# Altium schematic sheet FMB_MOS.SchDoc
size A3
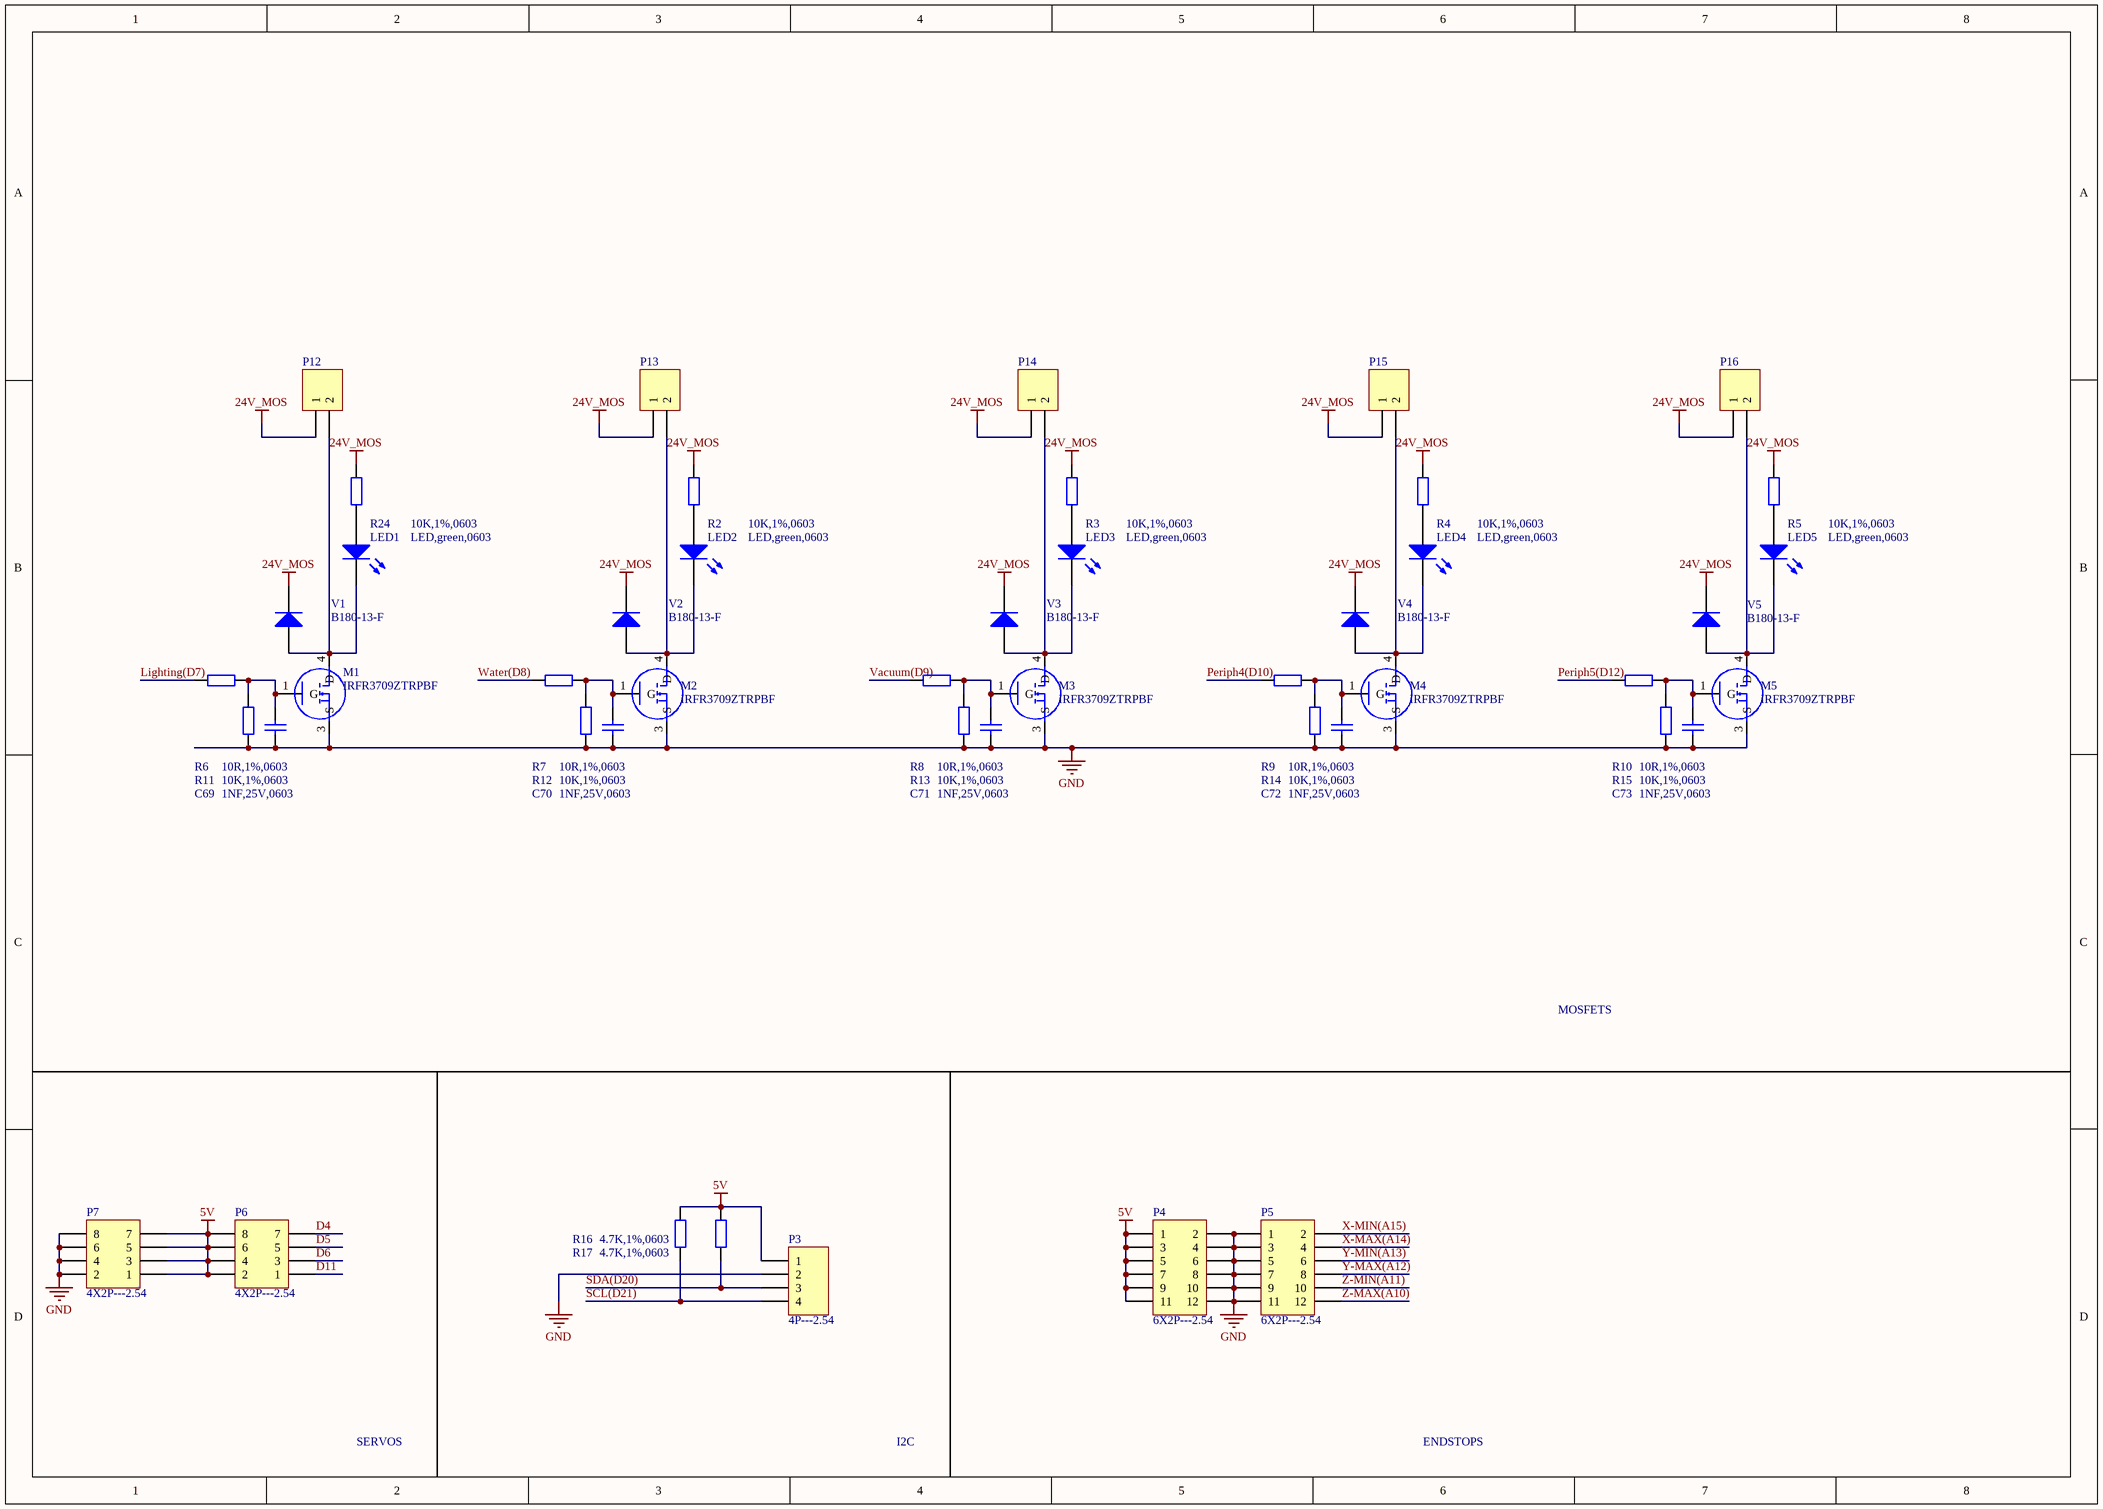
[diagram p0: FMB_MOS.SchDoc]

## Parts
C69  1NF,25V,0603  [RC0603]
C70  1NF,25V,0603  [RC0603]
C71  1NF,25V,0603  [RC0603]
C72  1NF,25V,0603  [RC0603]
C73  1NF,25V,0603  [RC0603]
LED1  LED,green,0603  [LED-0603]
LED2  LED,green,0603  [LED-0603]
LED3  LED,green,0603  [LED-0603]
LED4  LED,green,0603  [LED-0603]
LED5  LED,green,0603  [LED-0603]
M1  IRFR3709ZTRPBF  [DPAK]
M2  IRFR3709ZTRPBF  [DPAK]
M3  IRFR3709ZTRPBF  [DPAK]
M4  IRFR3709ZTRPBF  [DPAK]
M5  IRFR3709ZTRPBF  [DPAK]
P3  4P---2.54  [HDR1X4]
P4  6X2P---2.54  [HDR2X6]
P5  6X2P---2.54  [HDR2X6]
P6  4X2P---2.54  [HDR2X4]
P7  4X2P---2.54  [HDR2X4]
P12  Molex 151048-1206  [151048]  (value not drawn)
P13  Molex 151048-1206  [151048]  (value not drawn)
P14  Molex 151048-1206  [151048]  (value not drawn)
P15  Molex 151048-1206  [151048]  (value not drawn)
P16  Molex 151048-1206  [151048]  (value not drawn)
R2  10K,1%,0603  [RC0603]
R3  10K,1%,0603  [RC0603]
R4  10K,1%,0603  [RC0603]
R5  10K,1%,0603  [RC0603]
R6  10R,1%,0603  [RC0603]
R7  10R,1%,0603  [RC0603]
R8  10R,1%,0603  [RC0603]
R9  10R,1%,0603  [RC0603]
R10  10R,1%,0603  [RC0603]
R11  10K,1%,0603  [RC0603]
R12  10K,1%,0603  [RC0603]
R13  10K,1%,0603  [RC0603]
R14  10K,1%,0603  [RC0603]
R15  10K,1%,0603  [RC0603]
R16  4.7K,1%,0603  [RC0603]
R17  4.7K,1%,0603  [RC0603]
R24  10K,1%,0603  [RC0603]
V1  B180-13-F  [SMA]
V2  B180-13-F  [SMA]
V3  B180-13-F  [SMA]
V4  B180-13-F  [SMA]
V5  B180-13-F  [SMA]

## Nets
5V: P3.1 P4.1 P4.3 P4.5 P4.7 P4.9 P4.11 P6.2 P6.4 P6.6 P6.8 P7.1 P7.3 P7.5 P7.7 R16.2 R17.2
24V_MOS: P12.1 P13.1 P14.1 P15.1 P16.1 R2.1 R3.1 R4.1 R5.1 R24.1 V1.2(K) V2.2(K) V3.2(K) V4.2(K) V5.2(K)
GND: C69.1 C70.1 C71.1 C72.1 C73.1 M1.3(S) M2.3(S) M3.3(S) M4.3(S) M5.3(S) P3.2 P4.2 P4.4 P4.6 P4.8 P4.10 P4.12 P5.1 P5.3 P5.5 P5.7 P5.9 P5.11 P7.2 P7.4 P7.6 P7.8 R11.1 R12.1 R13.2 R14.1 R15.1
D4: P6.7
D5: P6.5
D6: P6.3
D11: P6.1
Lighting(D7): R6.1
Periph4(D10): R9.1
Periph5(D12): R10.1
SCL(D21): P3.4 R16.1
SDA(D20): P3.3 R17.1
Vacuum(D9): R8.1
Water(D8): R7.1
X-MAX(A14): P5.4
X-MIN(A15): P5.2
Y-MAX(A12): P5.8
Y-MIN(A13): P5.6
Z-MAX(A10): P5.12
Z-MIN(A11): P5.10
NetC69_2: C69.2 M1.1(G) R6.2 R11.2
NetC70_2: C70.2 M2.1(G) R7.2 R12.2
NetC71_2: C71.2 M3.1(G) R8.2 R13.1
NetC72_2: C72.2 M4.1(G) R9.2 R14.2
NetC73_2: C73.2 M5.1(G) R10.2 R15.2
NetLED1_1: LED1.1(A) R24.2
NetLED1_2: LED1.2(K) M1.4(D) P12.2 V1.1(A)
NetLED2_1: LED2.1(A) R2.2
NetLED2_2: LED2.2(K) M2.4(D) P13.2 V2.1(A)
NetLED3_1: LED3.1(A) R3.2
NetLED3_2: LED3.2(K) M3.4(D) P14.2 V3.1(A)
NetLED4_1: LED4.1(A) R4.2
NetLED4_2: LED4.2(K) M4.4(D) P15.2 V4.1(A)
NetLED5_1: LED5.1(A) R5.2
NetLED5_2: LED5.2(K) M5.4(D) P16.2 V5.1(A)

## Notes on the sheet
- MOSFETS
- SERVOS
- I2C
- ENDSTOPS

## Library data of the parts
C69-C73 = Cap: Capacitor; Value: 100pF
LED1-LED5 = LED0: Typical INFRARED GaAs LED
M1-M5 = AP94T07
P3 = Header 4: Header, 4-Pin
P4 P5 = Header 6X2: Header, 6-Pin, Dual row
P6 P7 = Header 4X2: Header, 4-Pin, Dual row
P12-P16 = Header 2: Header, 2-Pin
R2-R17 R24 = Res2: Resistor; Value: 1K
V1-V5 = Diode: Default Diode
